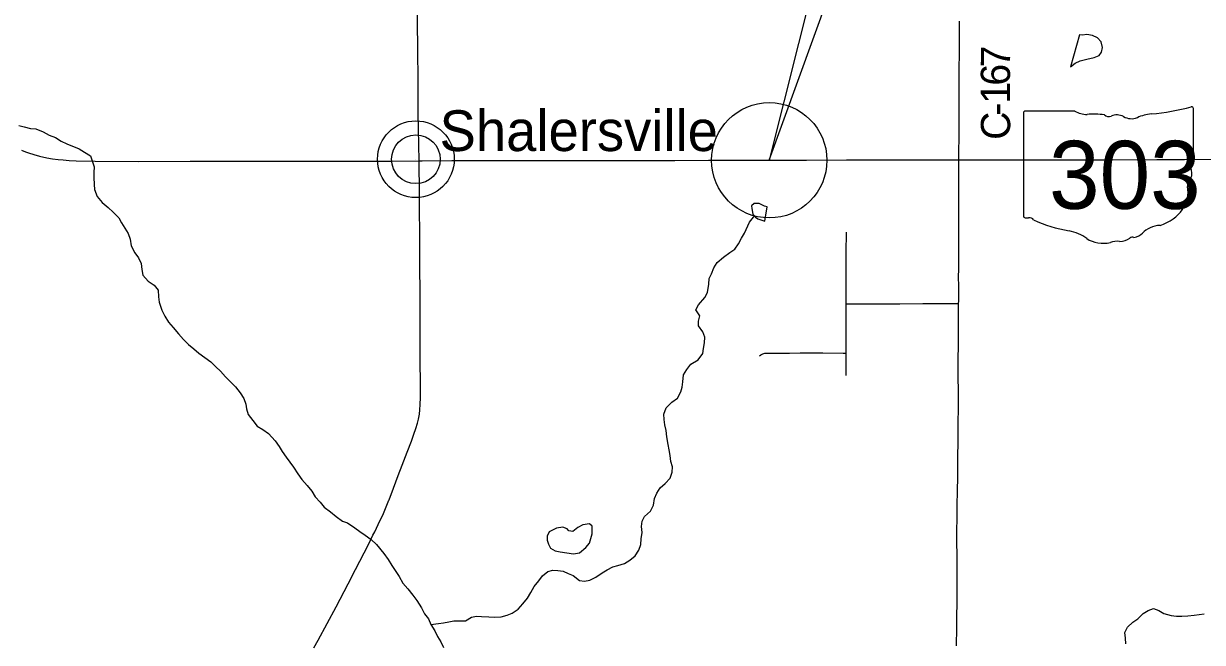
# Model space of a CAD drawing. Extents: x 0 to 34, y 0 to 22.
# Drawn here: x 25.975 to 28.262, y 17.236 to 18.436 of the extents above; entities that cross this region are included whole.
import ezdxf

# ---------------------------------------------------------------- set-up
doc = ezdxf.new("R2010")
doc.units = 0
for name, color, linetype in [('GM_X_County_Road', 7, 'Continuous'), ('GM_X_County_Road_Text', 7, 'Continuous'), ('GM_X_Minor_Lake', 7, 'Continuous'), ('GM_X_Minor_River', 7, 'Continuous'), ('GM_X_State_Location', 7, 'Continuous'), ('GM_X_State_Route', 7, 'Continuous'), ('GM_X_State_Shield', 7, 'Continuous'), ('GM_X_Township_Road', 7, 'Continuous'), ('GM_X_Unincorporated', 7, 'Continuous'), ('GM_X_Unincorporated_Location', 7, 'Continuous'), ('GM_X_Unincorporated_Text', 7, 'Continuous'), ('SH_Text', 7, 'Continuous')]:
    doc.layers.add(name, color=color, linetype=linetype)

msp = doc.modelspace()

# ---------------------------------------------------------------- linework, layer by layer
at = {"layer": 'GM_X_County_Road'}
for points in [[(27.7892, 18.1713), (27.79, 18.2311), (27.7902, 18.2746), (27.7903, 18.2982), (27.7899, 18.3224), (27.7902, 18.3491), (27.7904, 18.3765), (27.7906, 18.3945), (27.7906, 18.4026), (27.7907, 18.4249), (27.7908, 18.4405)], [(27.789, 17.893), (27.7892, 17.8975), (27.7895, 17.905), (27.7893, 17.923), (27.7891, 17.9279), (27.789, 17.9433), (27.7892, 17.961), (27.7893, 17.9746), (27.7894, 17.9826), (27.7895, 18.0011), (27.7893, 18.0123), (27.7895, 18.049), (27.7895, 18.1155), (27.7892, 18.1546), (27.7891, 18.1664), (27.7892, 18.1713)], [(27.7849, 17.2294), (27.7851, 17.2381), (27.7854, 17.2561), (27.7853, 17.2729), (27.7854, 17.2847), (27.786, 17.3145), (27.786, 17.3269), (27.7862, 17.3425), (27.7862, 17.3536), (27.7862, 17.3605), (27.7861, 17.3723), (27.7859, 17.376), (27.7859, 17.3917), (27.7859, 17.4052), (27.7859, 17.4094), (27.7858, 17.4135), (27.7857, 17.422), (27.7856, 17.4361), (27.7856, 17.4478), (27.7856, 17.4559), (27.7858, 17.4734), (27.7859, 17.4939), (27.7863, 17.5074), (27.7866, 17.5242), (27.7873, 17.5621), (27.7872, 17.5683), (27.7876, 17.6033), (27.7879, 17.6172), (27.7881, 17.6316), (27.7879, 17.6565), (27.7883, 17.6686), (27.7884, 17.6831), (27.7887, 17.6993), (27.7884, 17.7154), (27.7885, 17.7313), (27.7883, 17.7427), (27.7883, 17.7707), (27.7888, 17.826), (27.7889, 17.8639), (27.789, 17.893)]]:
    msp.add_lwpolyline(points, dxfattribs=at)
at = {"layer": 'GM_X_Minor_Lake'}
for p, q in [((28.0232, 18.4138), (28.006, 18.3517)), ((27.4128, 18.0528), (27.4175, 18.0802)), ((27.0158, 17.4116), (27.0421, 17.4079))]:
    msp.add_line(p, q, dxfattribs=at)
for points in [[(28.006, 18.3517), (28.0147, 18.3587), (28.0245, 18.3633), (28.0373, 18.3669), (28.052, 18.3697), (28.0615, 18.3736), (28.0663, 18.3802), (28.0681, 18.3893), (28.0653, 18.4003), (28.0581, 18.4082), (28.0485, 18.4126), (28.0375, 18.4144), (28.0292, 18.4135), (28.0232, 18.4138)], [(27.4175, 18.0802), (27.4121, 18.082), (27.4019, 18.0868), (27.3924, 18.0871), (27.3871, 18.0821), (27.3876, 18.0775), (27.39, 18.0665), (27.3949, 18.0605), (27.3995, 18.0575), (27.4128, 18.0528)], [(27.0421, 17.4079), (27.0534, 17.4098), (27.0657, 17.4198), (27.0732, 17.4286), (27.0783, 17.4466), (27.0782, 17.4617), (27.0728, 17.4662), (27.0603, 17.4642), (27.0505, 17.4588), (27.0404, 17.4514), (27.0332, 17.4525), (27.0294, 17.4562), (27.021, 17.4596), (27.0089, 17.4575), (26.995, 17.4505), (26.9909, 17.4421), (26.991, 17.4345), (26.9933, 17.4266), (26.9972, 17.4186), (27.0063, 17.4138), (27.0158, 17.4116)]]:
    msp.add_lwpolyline(points, dxfattribs=at)
at = {"layer": 'GM_X_Minor_River'}
for points in [[(25.9659, 18.2379), (25.9765, 18.2354), (25.989, 18.2325), (25.9993, 18.2319), (26.013, 18.2259), (26.0252, 18.2196), (26.0373, 18.2148), (26.0484, 18.2077), (26.0594, 18.2029), (26.083, 18.1926), (26.0937, 18.1866), (26.1048, 18.1792), (26.1091, 18.1678), (26.1122, 18.158), (26.1116, 18.147), (26.1113, 18.1375), (26.1122, 18.1238), (26.1131, 18.1143), (26.1181, 18.1007), (26.1277, 18.0891), (26.1396, 18.0789), (26.1492, 18.0699), (26.1599, 18.0594), (26.1653, 18.0496), (26.1784, 18.0285), (26.1819, 18.0175), (26.184, 18.0046), (26.1913, 17.9911), (26.1979, 17.9813), (26.2033, 17.9707), (26.2045, 17.9593), (26.2066, 17.9483), (26.2169, 17.9363), (26.2287, 17.9284), (26.2364, 17.9187), (26.237, 17.9058), (26.2386, 17.8955), (26.2433, 17.8804), (26.2491, 17.8683), (26.2564, 17.8566), (26.2653, 17.8468), (26.276, 17.8344), (26.2856, 17.8232), (26.2952, 17.8138), (26.3055, 17.8052), (26.315, 17.7969), (26.3269, 17.7887), (26.3383, 17.7797), (26.3479, 17.77), (26.3575, 17.7617), (26.3667, 17.7508), (26.3766, 17.7414), (26.3862, 17.7317), (26.3951, 17.72), (26.4028, 17.7087), (26.4067, 17.6981), (26.4075, 17.6886), (26.4107, 17.6776), (26.4199, 17.666), (26.4284, 17.6554), (26.4394, 17.6487), (26.4501, 17.6409), (26.4631, 17.627), (26.4708, 17.6161), (26.477, 17.6063), (26.4847, 17.5953), (26.492, 17.5856), (26.4989, 17.5758), (26.5074, 17.5626), (26.5147, 17.5516), (26.5251, 17.54), (26.5343, 17.5295), (26.5408, 17.5181), (26.5504, 17.508), (26.5585, 17.4982), (26.5703, 17.4892), (26.5814, 17.4799), (26.594, 17.4713), (26.6035, 17.4676)], [(26.7652, 17.2705), (26.7803, 17.273), (26.7901, 17.2738), (26.8003, 17.2762), (26.8101, 17.2782), (26.8211, 17.278), (26.8325, 17.2781), (26.8442, 17.2851), (26.854, 17.2867), (26.8638, 17.2865), (26.8779, 17.2859), (26.8896, 17.2852), (26.9017, 17.2854), (26.9134, 17.2886), (26.9232, 17.2928), (26.9349, 17.3006), (26.9435, 17.3106), (26.9528, 17.3217), (26.9595, 17.3331), (26.9658, 17.3446), (26.9744, 17.3553), (26.9815, 17.3649), (26.992, 17.3738), (27.0018, 17.3762), (27.0113, 17.3755), (27.0216, 17.3745), (27.0318, 17.3697), (27.0413, 17.3656), (27.0536, 17.3563), (27.0631, 17.3545), (27.0736, 17.3569), (27.0853, 17.3627), (27.0973, 17.3708), (27.1075, 17.377), (27.1184, 17.3828), (27.1282, 17.3849), (27.1407, 17.3888), (27.1512, 17.3954), (27.1614, 17.4042), (27.1684, 17.4146), (27.1725, 17.426), (27.1731, 17.4366), (27.1749, 17.4492), (27.1736, 17.4606), (27.1754, 17.4709), (27.1798, 17.4804), (27.1915, 17.4904), (27.197, 17.5019), (27.1991, 17.5148), (27.2036, 17.5251), (27.2103, 17.5358), (27.22, 17.5443), (27.2294, 17.5547), (27.2334, 17.5661), (27.2341, 17.5764), (27.2309, 17.587), (27.2296, 17.5987), (27.2273, 17.6093), (27.2256, 17.6195), (27.2232, 17.6343), (27.2219, 17.6468), (27.2191, 17.6578), (27.2175, 17.6684), (27.217, 17.6783), (27.2214, 17.6905), (27.2327, 17.7017), (27.2436, 17.7098), (27.2502, 17.7216), (27.2528, 17.7311), (27.2542, 17.741), (27.2556, 17.7547), (27.2619, 17.7654), (27.2697, 17.7754), (27.2836, 17.7839), (27.293, 17.7962), (27.294, 17.8057), (27.2961, 17.8171), (27.2968, 17.8281), (27.2925, 17.8383), (27.2844, 17.8496), (27.2847, 17.8591), (27.2872, 17.869), (27.2795, 17.8807), (27.2847, 17.8906), (27.2967, 17.9044), (27.3019, 17.9144), (27.3047, 17.9304), (27.3054, 17.9414), (27.3098, 17.9509), (27.3142, 17.9624), (27.3206, 17.9727), (27.3326, 17.9827), (27.3453, 17.992), (27.3551, 17.9985), (27.3622, 18.0089), (27.3681, 18.02), (27.3737, 18.0295), (27.3833, 18.0509), (27.3912, 18.0605), (27.3928, 18.0631)], [(26.6035, 17.4676), (26.6176, 17.4583), (26.6272, 17.4512), (26.6379, 17.4441), (26.6493, 17.4355), (26.6597, 17.4257), (26.6739, 17.4084), (26.6823, 17.3967), (26.6897, 17.3854), (26.6962, 17.3756), (26.7039, 17.364), (26.7112, 17.3508), (26.7205, 17.3398), (26.7304, 17.3278), (26.7381, 17.3176), (26.747, 17.3033), (26.7528, 17.2916), (26.7609, 17.2815), (26.7652, 17.2705), (26.7733, 17.2584), (26.7779, 17.2475), (26.7845, 17.2373), (26.7899, 17.2264)], [(28.1135, 17.2331), (28.1123, 17.2445), (28.1114, 17.2555), (28.1162, 17.2658), (28.1267, 17.2754), (28.1365, 17.282), (28.1466, 17.292), (28.1564, 17.2978), (28.1669, 17.3017), (28.1772, 17.298), (28.1871, 17.2924), (28.2012, 17.2884), (28.2114, 17.287), (28.222, 17.2871), (28.2334, 17.2877), (28.2459, 17.2889), (28.2655, 17.2915)]]:
    msp.add_lwpolyline(points, dxfattribs=at)
at = {"layer": 'GM_X_State_Route'}
for points in [[(26.7425, 18.1697), (26.7409, 18.2627), (26.7404, 18.3254), (26.7398, 18.3845), (26.7389, 18.4957), (26.7384, 18.5326), (26.7382, 18.5588)], [(25.971, 18.1903), (25.979, 18.1869), (25.985, 18.1849), (25.995, 18.1818), (26.0064, 18.1788), (26.0203, 18.1756), (26.0312, 18.1738), (26.0423, 18.1723), (26.0522, 18.1715), (26.064, 18.1705), (26.077, 18.1697), (26.1141, 18.1687), (26.1986, 18.1685), (26.2986, 18.1688), (26.3823, 18.169)], [(26.3823, 18.169), (26.4352, 18.1692), (26.4879, 18.1692), (26.5482, 18.1689), (26.6904, 18.169), (26.7425, 18.1697)], [(26.6839, 17.5118), (26.6842, 17.5127), (26.6928, 17.5354), (26.702, 17.5598), (26.7094, 17.5795), (26.7191, 17.6051), (26.7274, 17.6265), (26.7325, 17.6399), (26.7363, 17.651), (26.7393, 17.6611), (26.7412, 17.6689), (26.743, 17.6786), (26.7441, 17.6872), (26.7448, 17.6971), (26.7452, 17.7107), (26.7448, 17.8085), (26.7447, 17.8918), (26.744, 17.9868), (26.7437, 18.029), (26.7435, 18.0753), (26.7434, 18.1056), (26.7425, 18.1697)], [(26.7425, 18.1697), (26.7482, 18.1698), (26.806, 18.17), (26.8563, 18.17), (26.9091, 18.1701), (26.9557, 18.1701), (27.0122, 18.1702), (27.0514, 18.1702), (27.1415, 18.1705), (27.1857, 18.1703), (27.2385, 18.1706), (27.3037, 18.1708), (27.3571, 18.1707), (27.3944, 18.1707), (27.4361, 18.1707), (27.4939, 18.1712), (27.5715, 18.1714), (27.5945, 18.1715), (27.6336, 18.1714), (27.7713, 18.1713), (27.7892, 18.1713), (27.7986, 18.1713), (27.8805, 18.1713), (27.9874, 18.1714), (28.0738, 18.1718), (28.1731, 18.1723), (28.2271, 18.1725), (28.2945, 18.1727)], [(26.6188, 17.3773), (26.644, 17.4261), (26.653, 17.4438), (26.6565, 17.4507), (26.6666, 17.4716), (26.6719, 17.4829), (26.6787, 17.4989), (26.6839, 17.5118)], [(26.5386, 17.2253), (26.5469, 17.2406), (26.5642, 17.2729), (26.5813, 17.3053), (26.6046, 17.3499), (26.6188, 17.3773)]]:
    msp.add_lwpolyline(points, dxfattribs=at)
at = {"layer": 'GM_X_State_Shield'}
for p, q in [((28.2444, 18.1663), (28.2444, 18.271)), ((27.9148, 18.2626), (27.9148, 18.0625)), ((28.0146, 18.266), (27.9181, 18.266)), ((28.2444, 18.1663), (28.2444, 18.1663))]:
    msp.add_line(p, q, dxfattribs=at)
for centre, major_axis, start_param, end_param in [((28.127, 18.5389), (0.3495, 0), 4.814394, 5.042369), ((28.2407, 18.2714), (0.00367, 0), 6.141152, 7.989035), ((27.9186, 18.263), (0.00382, 0), 1.712693, 3.28349), ((28.0376, 18.2893), (0.037, 0), 4.042523, 4.731795), ((28.0498, 18.1537), (0.133, 0), 1.404758, 1.657858), ((28.08, 18.2641), (0.0107, 0), 3.836095, 5.185415), ((28.0957, 18.2409), (0.0222, 0), 0.950623, 2.079405), ((28.1244, 18.2727), (0.0267, 0), 4.081561, 5.145723), ((28.1716, 18.2049), (0.0703, 0), 1.699011, 2.107814), ((28.2435, 18.1586), (0.00568, 0), 1.883978, 3.671073), ((28.2074, 18.1454), (0.0341, 0), 5.934695, 6.695948), ((28.2405, 18.1659), (0.00393, 0), 5.05454, 6.418171), ((28.2575, 18.1225), (0.0248, 0), 2.387724, 3.262537), ((28.1466, 18.1092), (0.0874, 0), 5.101752, 6.440018), ((27.9186, 18.062), (0.00385, 0), 3.00124, 4.508301), ((27.9192, 18.0825), (0.0294, 0), 4.665946, 4.897461), ((27.9252, 18.0509), (0.0106, 0), 0.519207, 1.627899), ((28.059, 18.2307), (0.2524, 0), 4.195997, 4.488961), ((28.1834, 18.0063), (0.0479, 0), 1.647645, 2.488434), ((27.9838, 17.9726), (0.079, 0), 0.823519, 1.323587), ((28.0692, 18.0499), (0.0501, 0), 4.026481, 4.996735), ((28.1018, 18.0349), (0.0267, 0), 4.691044, 5.507374), ((28.126, 18.0156), (0.00752, 0), 1.147584, 2.315152), ((28.1228, 18.0431), (0.0282, 0), 4.937069, 5.64225), ((28.0982, 17.9807), (0.0412, 0), 1.495662, 1.94098)]:
    msp.add_ellipse(centre, major_axis=major_axis, ratio=0.8, start_param=start_param, end_param=end_param, dxfattribs=at)
at = {"layer": 'GM_X_Township_Road'}
for points in [[(27.5707, 17.8924), (27.5707, 17.8941), (27.571, 17.9326), (27.5711, 17.9593), (27.5711, 17.976), (27.5711, 17.9996), (27.5713, 18.0232), (27.5713, 18.0313)], [(27.5711, 17.797), (27.5711, 17.8196), (27.5708, 17.8314), (27.5706, 17.8624), (27.5706, 17.8748), (27.5707, 17.8924)], [(27.5707, 17.8924), (27.5768, 17.8924), (27.6066, 17.8924), (27.675, 17.8926), (27.7197, 17.8931), (27.789, 17.893)], [(27.4025, 17.7916), (27.4056, 17.7936), (27.4095, 17.7955), (27.4113, 17.7962), (27.4131, 17.7965), (27.418, 17.7969), (27.4323, 17.7969), (27.4503, 17.7968), (27.4609, 17.7969), (27.4819, 17.7974), (27.5024, 17.7976), (27.5254, 17.7973), (27.5651, 17.797), (27.5711, 17.797)], [(27.5707, 17.7538), (27.5711, 17.7855), (27.5711, 17.797)]]:
    msp.add_lwpolyline(points, dxfattribs=at)
at = {"layer": 'GM_X_Unincorporated'}
for radius in [0.0744, 0.0472]:
    msp.add_circle((26.7362, 18.1727), radius, dxfattribs=at)
at = {"layer": 'GM_X_Unincorporated_Location'}
msp.add_line((26.7362, 18.1727), (26.7362, 18.1727), dxfattribs=at)
at = {"layer": 'SH_Text'}
msp.add_lwpolyline([(27.9346, 20.2119), (27.4216, 18.1707), (28.1627, 20.2119), (27.9346, 20.2119)], dxfattribs=at)
msp.add_circle((27.4216, 18.1707), 0.1118, dxfattribs=at)

# ---------------------------------------------------------------- texts
at = {"layer": 'GM_X_County_Road_Text'}
for s, rotation, p in [('7', 89.3599, (27.8887, 18.3502)), ('6', 89.8074, (27.8886, 18.3153)), ('1', 90.1249, (27.8887, 18.2804)), ('-', 90.3279, (27.8888, 18.2571)), ('C', 90.4098, (27.8892, 18.2105))]:
    msp.add_text(s, height=0.0568, rotation=rotation, dxfattribs=at).set_placement(p)
at = {"layer": 'GM_X_State_Location'}
msp.add_text('303', height=0.000189, rotation=0, dxfattribs=at).set_placement((28.009, 18.1354))
for s in ['s', 'r']:
    msp.add_text(s, height=0.000189, dxfattribs=at).set_placement((28.0759, 18.1492))
at = {"layer": 'GM_X_State_Shield'}
msp.add_text('303', height=0.13184, dxfattribs=at).set_placement((27.9643, 18.0766))
at = {"layer": 'GM_X_Unincorporated_Text'}
msp.add_text('Shalersville', height=0.078977, rotation=0, dxfattribs=at).set_placement((26.7821, 18.1886))

doc.saveas('drawing.dxf')
